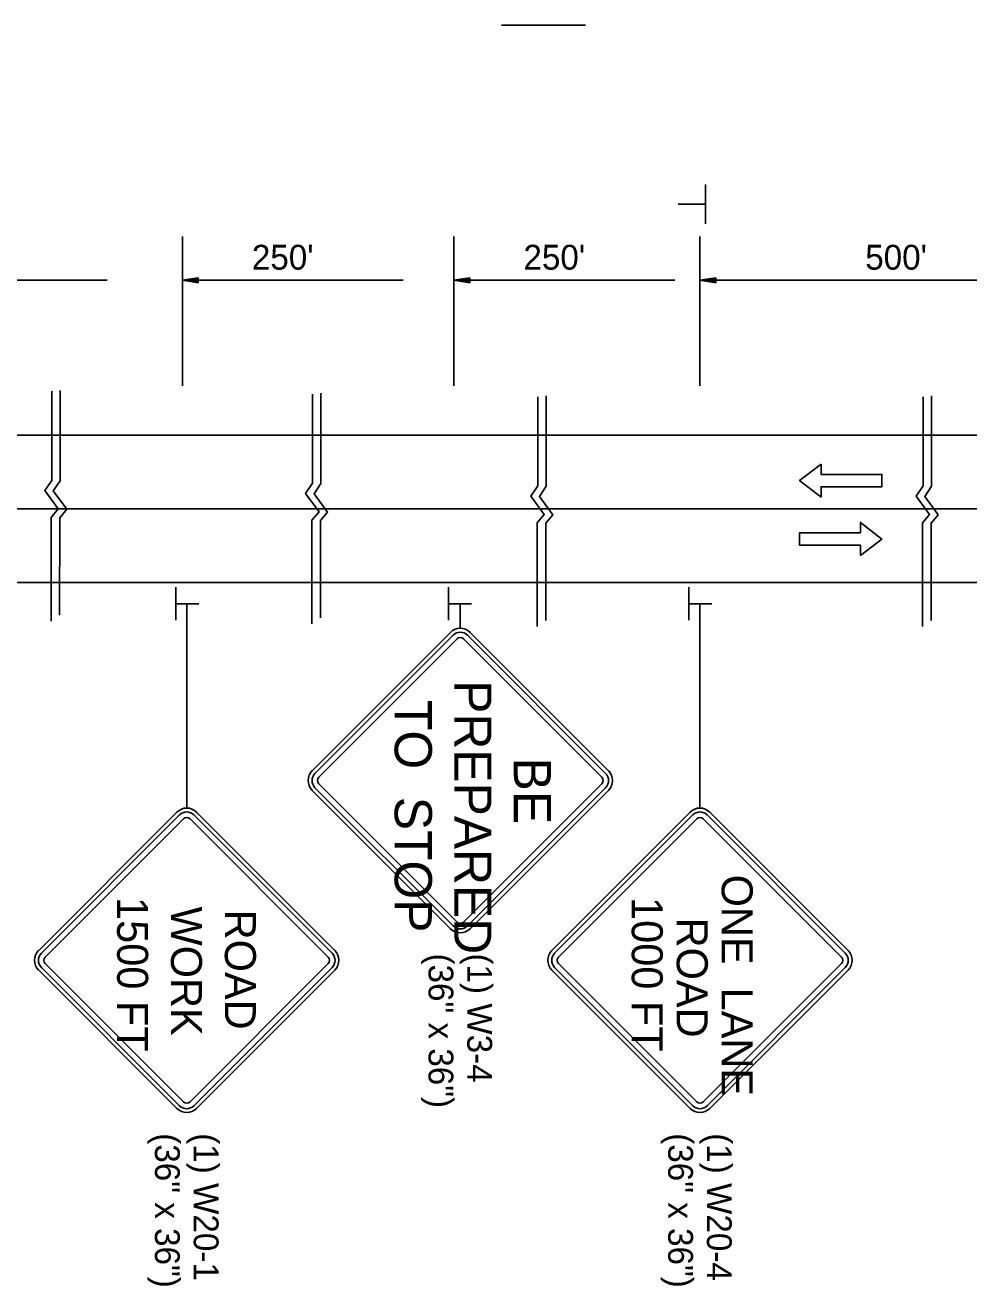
# Model space of a CAD drawing. Extents: x 1930579 to 1934718, y 596452 to 597844.
# Drawn here: x 1932705.4 to 1932933.5, y 597226 to 597530.6 of the extents above; entities that cross this region are included whole.
import ezdxf

# ---------------------------------------------------------------- set-up
doc = ezdxf.new("R2010")
doc.units = 0
for name, color, linetype in [('Default', 7, 'Continuous'), ('P_TC_Signs_Permanent', 7, 'Continuous'), ('P_TC_Signs_Temporary', 7, 'Continuous'), ('R_Annotation', 7, 'Continuous'), ('R_Striping', 7, 'Continuous')]:
    doc.layers.add(name, color=color, linetype=linetype)

msp = doc.modelspace()

# ---------------------------------------------------------------- linework, layer by layer
at = {"layer": 'Default'}
for p, q in [((1932869.84, 597492.1), (1932869.84, 597482.61)), ((1932869.7, 597487.37), (1932863.22, 597487.37)), ((1932743.37, 597479.5), (1932743.37, 597443.47)), ((1932809.02, 597479.5), (1932809.02, 597443.47)), ((1932868.48, 597479.5), (1932868.48, 597443.47)), ((1932671.78, 597468.94), (1932725.18, 597468.94)), ((1932747.21, 597469.52), (1932743.37, 597468.94)), ((1932743.37, 597468.94), (1932796.77, 597468.94)), ((1932747.21, 597468.36), (1932743.37, 597468.94)), ((1932747.21, 597469.42), (1932744.01, 597468.94)), ((1932747.21, 597468.46), (1932744.01, 597468.94)), ((1932747.21, 597469.32), (1932744.67, 597468.94)), ((1932747.21, 597468.56), (1932744.67, 597468.94)), ((1932747.21, 597469.23), (1932745.31, 597468.94)), ((1932747.21, 597468.65), (1932745.31, 597468.94)), ((1932747.21, 597469.13), (1932745.96, 597468.94)), ((1932747.21, 597468.75), (1932745.96, 597468.94)), ((1932747.21, 597469.03), (1932746.6, 597468.94)), ((1932747.21, 597468.85), (1932746.6, 597468.94)), ((1932747.21, 597468.36), (1932747.21, 597469.52)), ((1932812.86, 597469.52), (1932809.02, 597468.94)), ((1932809.02, 597468.94), (1932862.43, 597468.94)), ((1932812.86, 597468.36), (1932809.02, 597468.94)), ((1932812.86, 597469.42), (1932809.67, 597468.94)), ((1932812.86, 597468.46), (1932809.67, 597468.94)), ((1932812.86, 597469.32), (1932810.33, 597468.94)), ((1932812.86, 597468.56), (1932810.33, 597468.94)), ((1932812.86, 597469.23), (1932810.96, 597468.94)), ((1932812.86, 597468.65), (1932810.96, 597468.94)), ((1932812.86, 597469.13), (1932811.61, 597468.94)), ((1932812.86, 597468.75), (1932811.61, 597468.94)), ((1932812.86, 597469.03), (1932812.26, 597468.94)), ((1932812.86, 597468.85), (1932812.26, 597468.94)), ((1932812.86, 597468.36), (1932812.86, 597469.52)), ((1932872.31, 597469.52), (1932868.48, 597468.94)), ((1932868.48, 597468.94), (1932968.23, 597468.94)), ((1932872.31, 597468.36), (1932868.48, 597468.94)), ((1932872.31, 597469.42), (1932869.12, 597468.94)), ((1932872.31, 597468.46), (1932869.12, 597468.94)), ((1932872.31, 597469.32), (1932869.78, 597468.94)), ((1932872.31, 597468.56), (1932869.78, 597468.94)), ((1932872.31, 597469.23), (1932870.42, 597468.94)), ((1932872.31, 597468.65), (1932870.42, 597468.94)), ((1932872.31, 597469.13), (1932871.07, 597468.94)), ((1932872.31, 597468.75), (1932871.07, 597468.94)), ((1932872.31, 597469.03), (1932871.71, 597468.94)), ((1932872.31, 597468.85), (1932871.71, 597468.94)), ((1932872.31, 597468.36), (1932872.31, 597469.52)), ((1932535.52, 597431.5), (1933637.52, 597431.5)), ((1932443.39, 597413.71), (1933637.52, 597413.71)), ((1932535.52, 597395.93), (1933637.52, 597395.93)), ((1932741.75, 597386.79), (1932741.75, 597394.79)), ((1932807.71, 597386.79), (1932807.71, 597394.79)), ((1932865.83, 597386.79), (1932865.83, 597394.79)), ((1932741.87, 597390.77), (1932747.33, 597390.77)), ((1932807.83, 597390.77), (1932813.3, 597390.77)), ((1932865.94, 597390.77), (1932871.41, 597390.77))]:
    msp.add_line(p, q, dxfattribs=at)
for points in [[(1932711.78, 597442.11), (1932711.78, 597420.58), (1932710.12, 597418.11), (1932713.36, 597413.68), (1932711.65, 597411.64), (1932711.65, 597386.61)], [(1932713.83, 597442.3), (1932713.83, 597420.5), (1932712.16, 597418.03), (1932715.4, 597413.6), (1932713.7, 597411.55), (1932713.69, 597388.05)], [(1932774.82, 597441.44), (1932774.82, 597419.91), (1932773.16, 597417.44), (1932776.4, 597413.01), (1932774.69, 597410.97), (1932774.69, 597385.94)], [(1932776.87, 597441.63), (1932776.87, 597419.83), (1932775.21, 597417.36), (1932778.44, 597412.93), (1932776.74, 597410.88), (1932776.74, 597387.38)], [(1932829.28, 597440.79), (1932829.28, 597419.27), (1932827.62, 597416.8), (1932830.86, 597412.37), (1932829.16, 597410.32), (1932829.15, 597385.29)], [(1932831.33, 597440.99), (1932831.33, 597419.18), (1932829.67, 597416.71), (1932832.9, 597412.28), (1932831.2, 597410.23), (1932831.2, 597386.73)], [(1932922.45, 597440.79), (1932922.45, 597419.27), (1932920.79, 597416.8), (1932924.02, 597412.37), (1932922.32, 597410.32), (1932922.31, 597385.29)], [(1932924.49, 597440.99), (1932924.49, 597419.18), (1932922.83, 597416.71), (1932926.07, 597412.28), (1932924.36, 597410.23), (1932924.36, 597386.73)]]:
    msp.add_lwpolyline(points, dxfattribs=at)
at = {"layer": 'P_TC_Signs_Permanent'}
for p, q in [((1932808.18, 597383.86), (1932774.77, 597350.45)), ((1932808.84, 597383.2), (1932775.43, 597349.79)), ((1932845.7, 597349.79), (1932812.29, 597383.2)), ((1932846.36, 597350.45), (1932812.95, 597383.86)), ((1932809.77, 597382.27), (1932776.36, 597348.86)), ((1932844.77, 597348.86), (1932811.36, 597382.27)), ((1932775.43, 597346.34), (1932808.84, 597312.93)), ((1932776.36, 597347.27), (1932809.77, 597313.86)), ((1932811.36, 597313.86), (1932844.77, 597347.27)), ((1932812.29, 597312.93), (1932845.7, 597346.34)), ((1932774.77, 597345.68), (1932808.18, 597312.27)), ((1932812.95, 597312.27), (1932846.36, 597345.68))]:
    msp.add_line(p, q, dxfattribs=at)
for centre, radius, start, end in [((1932810.56, 597381.48), 3.38, 45, 135), ((1932810.56, 597381.48), 2.44, 45, 135), ((1932810.56, 597381.48), 1.13, 45, 135), ((1932777.15, 597348.07), 3.38, 135, 225), ((1932777.15, 597348.07), 2.44, 135, 225), ((1932843.97, 597348.07), 2.44, 315, 45), ((1932843.97, 597348.07), 3.38, 315, 45), ((1932777.15, 597348.07), 1.13, 135, 225), ((1932843.97, 597348.07), 1.13, 315, 45), ((1932810.56, 597314.66), 2.44, 225, 315), ((1932810.56, 597314.66), 1.13, 225, 315), ((1932810.56, 597314.66), 3.38, 225, 315)]:
    msp.add_arc(centre, radius, start, end, dxfattribs=at)
at = {"layer": 'P_TC_Signs_Temporary'}
for p, q in [((1932820.55, 597530.57), (1932840.8, 597530.57)), ((1932708.63, 597307.02), (1932742.04, 597340.43)), ((1932746.81, 597340.43), (1932780.22, 597307.02)), ((1932832.71, 597307.02), (1932866.12, 597340.43)), ((1932870.89, 597340.43), (1932904.3, 597307.02)), ((1932709.29, 597306.36), (1932742.7, 597339.77)), ((1932710.22, 597305.43), (1932743.63, 597338.84)), ((1932745.22, 597338.84), (1932778.63, 597305.43)), ((1932746.15, 597339.77), (1932779.56, 597306.36)), ((1932833.37, 597306.36), (1932866.78, 597339.77)), ((1932834.3, 597305.43), (1932867.71, 597338.84)), ((1932869.3, 597338.84), (1932902.71, 597305.43)), ((1932870.23, 597339.77), (1932903.64, 597306.36)), ((1932743.63, 597270.43), (1932710.22, 597303.84)), ((1932778.63, 597303.84), (1932745.22, 597270.43)), ((1932867.71, 597270.43), (1932834.3, 597303.84)), ((1932902.71, 597303.84), (1932869.3, 597270.43)), ((1932742.04, 597268.83), (1932708.63, 597302.25)), ((1932742.7, 597269.5), (1932709.29, 597302.91)), ((1932779.56, 597302.91), (1932746.15, 597269.5)), ((1932780.22, 597302.25), (1932746.81, 597268.83)), ((1932866.12, 597268.83), (1932832.71, 597302.25)), ((1932866.78, 597269.5), (1932833.37, 597302.91)), ((1932903.64, 597302.91), (1932870.23, 597269.5)), ((1932904.3, 597302.25), (1932870.89, 597268.83))]:
    msp.add_line(p, q, dxfattribs=at)
for centre, radius, start, end in [((1932744.42, 597338.04), 3.38, 45, 135), ((1932744.42, 597338.04), 2.44, 45, 135), ((1932868.5, 597338.04), 3.38, 45, 135), ((1932868.5, 597338.04), 2.44, 45, 135), ((1932744.42, 597338.04), 1.12, 45, 135), ((1932868.5, 597338.04), 1.12, 45, 135), ((1932711.01, 597304.63), 3.38, 135, 225), ((1932777.83, 597304.63), 3.38, 315, 45), ((1932835.09, 597304.63), 3.38, 135, 225), ((1932901.91, 597304.63), 3.38, 315, 45), ((1932711.01, 597304.63), 2.44, 135, 225), ((1932711.01, 597304.63), 1.13, 135, 225), ((1932777.83, 597304.63), 1.13, 315, 45), ((1932777.83, 597304.63), 2.44, 315, 45), ((1932835.09, 597304.63), 2.44, 135, 225), ((1932835.09, 597304.63), 1.13, 135, 225), ((1932901.91, 597304.63), 1.13, 315, 45), ((1932901.91, 597304.63), 2.44, 315, 45), ((1932744.42, 597271.22), 1.12, 225, 315), ((1932868.5, 597271.22), 1.12, 225, 315), ((1932744.42, 597271.22), 3.38, 225, 315), ((1932744.42, 597271.22), 2.44, 225, 315), ((1932868.5, 597271.22), 3.38, 225, 315), ((1932868.5, 597271.22), 2.44, 225, 315)]:
    msp.add_arc(centre, radius, start, end, dxfattribs=at)
at = {"layer": 'R_Annotation'}
for p, q in [((1932744.42, 597390.94), (1932744.42, 597341.42)), ((1932810.56, 597390.77), (1932810.56, 597384.85)), ((1932868.5, 597390.94), (1932868.5, 597341.42))]:
    msp.add_line(p, q, dxfattribs=at)
at = {"layer": 'R_Striping'}
for points in [[(1932897.77, 597424.55), (1932892.58, 597420.55), (1932897.77, 597416.55), (1932897.77, 597419.05), (1932912.48, 597419.05), (1932912.48, 597422.05), (1932897.77, 597422.05)], [(1932907.29, 597402.42), (1932912.48, 597406.42), (1932907.29, 597410.42), (1932907.29, 597407.92), (1932892.58, 597407.92), (1932892.58, 597404.92), (1932907.29, 597404.92)]]:
    msp.add_lwpolyline(points, close=True, dxfattribs=at)

# ---------------------------------------------------------------- texts
at = {"layer": 'Default'}
for s, p in [("250'", (1932760.17, 597471.51)), ("250'", (1932825.83, 597471.51)), ("500'", (1932908.46, 597471.51))]:
    msp.add_text(s, height=6, rotation=360, dxfattribs=at).set_placement(p)
at = {"layer": 'P_TC_Signs_Temporary'}
for s, height, p in [('PREPARED', 9, (1932809.09, 597372.31)), ('TO  STOP', 9, (1932794.69, 597367.53)), ('BE', 9, (1932823.49, 597353.62)), ('ONE  LANE', 7.5, (1932873.75, 597325.33)), ('1500 FT', 7.5, (1932727.59, 597319.92)), ('1000 FT', 7.5, (1932852, 597319.92)), ('WORK', 7.5, (1932740.61, 597317.62)), (' ROAD ', 7.5, (1932753.64, 597319.65)), ('ROAD', 7.5, (1932862.88, 597314.94))]:
    msp.add_text(s, height=height, rotation=270, dxfattribs=at).set_placement(p)
at = {"layer": 'R_Annotation'}
for s, height, p in [('(36" x 36")', 5.9996, (1932802.88, 597306.28)), ('(1) W3-4', 6, (1932812.25, 597306.28)), ('(36" x 36")', 5.9996, (1932736.74, 597262.85)), ('(1) W20-1', 6, (1932746.11, 597262.85)), ('(36" x 36")', 5.9996, (1932860.82, 597262.85)), ('(1) W20-4', 6, (1932870.18, 597262.85))]:
    msp.add_text(s, height=height, rotation=270, dxfattribs=at).set_placement(p)

doc.saveas('drawing.dxf')
